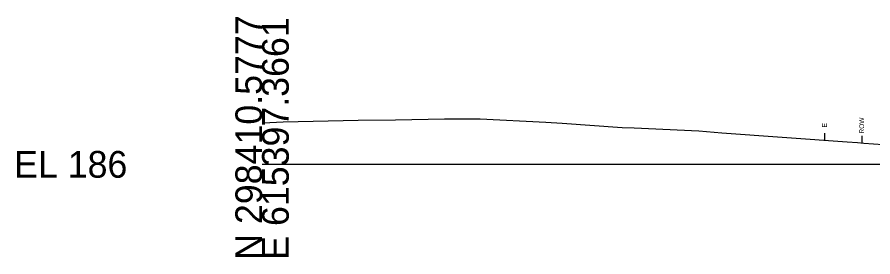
# Model space of a CAD drawing. Extents: x 517327 to 517505, y 114839 to 117370.
# Drawn here: x 517326.7 to 517416.4, y 116338.7 to 116363.8 of the extents above; entities that cross this region are included whole.
import ezdxf

# ---------------------------------------------------------------- set-up
doc = ezdxf.new("R2010")
doc.units = 0
for name, color, linetype in [('Exist XS Ground Line', 7, 'Continuous'), ('Old_Level_63', 7, 'Continuous'), ('Prop XS Exc Vertical Line 1', 7, 'Continuous'), ('Prop XS Exc Vertical Line 2', 7, 'Continuous')]:
    doc.layers.add(name, color=color, linetype=linetype)

msp = doc.modelspace()

# ---------------------------------------------------------------- linework, layer by layer
at = {"layer": 'Exist XS Ground Line'}
for p, q in [((517362.43, 116352.977), (517366.355, 116353.037)), ((517366.355, 116353.037), (517371.508, 116353.132)), ((517371.508, 116353.132), (517375.253, 116353.129)), ((517375.253, 116353.129), (517382.139, 116352.793)), ((517352.365, 116352.708), (517353.187, 116352.748)), ((517353.187, 116352.748), (517354.591, 116352.815)), ((517354.591, 116352.815), (517362.43, 116352.977)), ((517382.139, 116352.793), (517383.859, 116352.675)), ((517383.859, 116352.675), (517390.144, 116352.239)), ((517390.144, 116352.239), (517391.398, 116352.179)), ((517391.398, 116352.179), (517398.167, 116351.865)), ((517398.167, 116351.865), (517400.599, 116351.652)), ((517400.599, 116351.652), (517413.757, 116350.72)), ((517413.757, 116350.72), (517414.832, 116350.635)), ((517414.832, 116350.635), (517415.494, 116350.598)), ((517415.494, 116350.598), (517418.927, 116350.355))]:
    msp.add_line(p, q, dxfattribs=at)
at = {"layer": 'Old_Level_63'}
msp.add_line((517352.365, 116348.365), (517427.365, 116348.365), dxfattribs=at)
at = {"layer": 'Prop XS Exc Vertical Line 1'}
msp.add_line((517411.363, 116351.639), (517411.363, 116350.889), dxfattribs=at)
at = {"layer": 'Prop XS Exc Vertical Line 2'}
msp.add_line((517415.269, 116351.36), (517415.269, 116350.61), dxfattribs=at)

# ---------------------------------------------------------------- texts
at = {"layer": 'Old_Level_63'}
for s, p in [('N 298410.5777', (517352.365, 116338.365)), ('E 615397.3661', (517355.165, 116338.365))]:
    msp.add_text(s, height=2.8, rotation=90, dxfattribs=at).set_placement(p)
msp.add_text('EL 186', height=2.8, dxfattribs=at).set_placement((517326.362, 116346.965))
at = {"layer": 'Prop XS Exc Vertical Line 1'}
msp.add_text('E', height=0.5, rotation=90, dxfattribs=at).set_placement((517411.613, 116352.232))
at = {"layer": 'Prop XS Exc Vertical Line 2'}
msp.add_text('ROW', height=0.5, rotation=90, dxfattribs=at).set_placement((517415.519, 116351.585))

doc.saveas('drawing.dxf')
